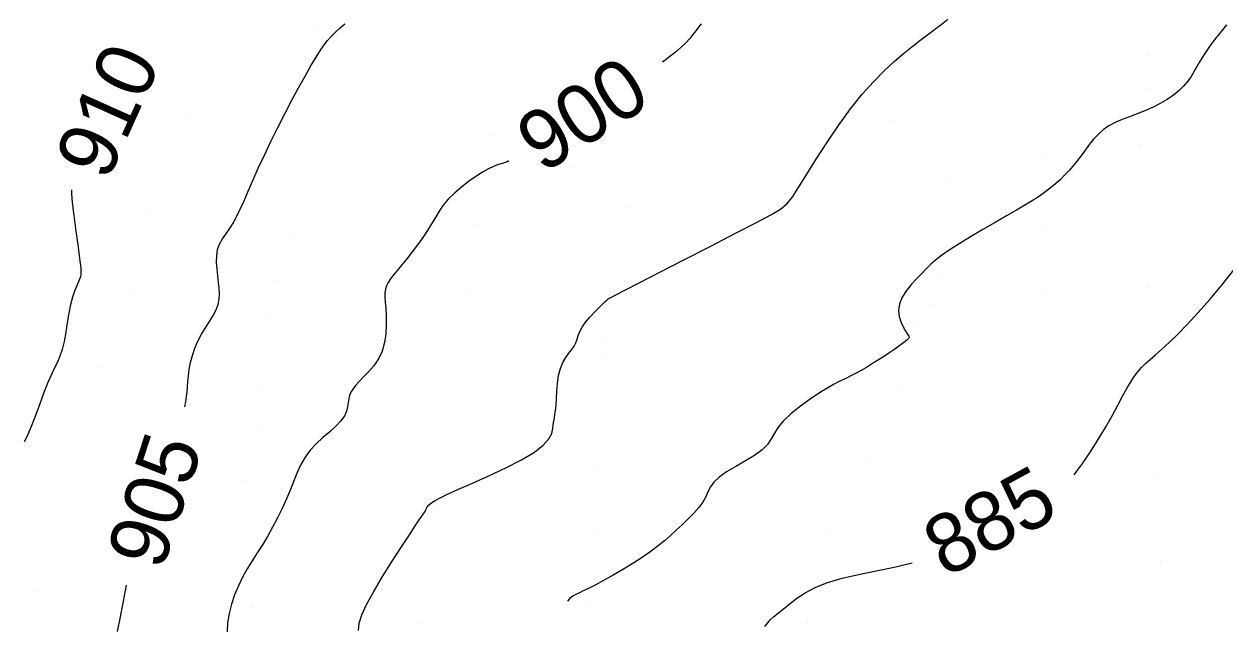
# Model space of a CAD drawing. Extents: x 400243 to 403697, y 4403637 to 4408083.
# Drawn here: x 402560 to 402712.4, y 4406302.1 to 4406378.5 of the extents above; entities that cross this region are included whole.
import ezdxf

# ---------------------------------------------------------------- set-up
doc = ezdxf.new("R2010")
doc.units = 0
doc.layers.add('HH_IC', color=7, linetype='Continuous')

msp = doc.modelspace()

# ---------------------------------------------------------------- linework, layer by layer
at = {"layer": 'HH_IC'}
for p, q in [((402596.95, 4406377.82), (402596.95, 4406377.82)), ((402613.38, 4406373.82), (402613.38, 4406373.82)), ((402702.61, 4406374.49), (402702.61, 4406374.49)), ((402689.11, 4406370.93), (402689.11, 4406370.93)), ((402702.76, 4406370.28), (402702.76, 4406370.28)), ((402599.34, 4406367.55), (402599.34, 4406367.55)), ((402580.57, 4406367), (402580.57, 4406367)), ((402670.6, 4406366.18), (402670.6, 4406366.18)), ((402619.51, 4406364.32), (402619.51, 4406364.32)), ((402701.52, 4406363.23), (402701.52, 4406363.23)), ((402689.31, 4406361.93), (402689.31, 4406361.93)), ((402621.3, 4406361.21), (402621.3, 4406361.21)), ((402629.18, 4406360.32), (402629.18, 4406360.32)), ((402676.82, 4406358.81), (402676.82, 4406358.81)), ((402631.27, 4406355.75), (402631.27, 4406355.75)), ((402575.44, 4406354.78), (402575.44, 4406354.78)), ((402636.48, 4406355.24), (402636.48, 4406355.24)), ((402656.96, 4406355.17), (402656.96, 4406355.17)), ((402702.32, 4406354.65), (402702.32, 4406354.65)), ((402617.11, 4406352.94), (402617.11, 4406352.94)), ((402689.86, 4406352.63), (402689.86, 4406352.63)), ((402594.46, 4406351.36), (402594.46, 4406351.36)), ((402675.85, 4406346.66), (402675.85, 4406346.66)), ((402592.23, 4406345.91), (402592.23, 4406345.91)), ((402616.71, 4406344.69), (402616.71, 4406344.69)), ((402702.71, 4406344.99), (402702.71, 4406344.99)), ((402573.45, 4406344.59), (402573.45, 4406344.59)), ((402634.3, 4406343.52), (402634.3, 4406343.52)), ((402689, 4406344.3), (402689, 4406344.3)), ((402674.7, 4406342.75), (402674.7, 4406342.75)), ((402591.18, 4406341.19), (402591.18, 4406341.19)), ((402672.69, 4406340.34), (402672.69, 4406340.34)), ((402633.27, 4406338.61), (402633.27, 4406338.61)), ((402672.01, 4406338.84), (402672.01, 4406338.84)), ((402633.12, 4406336.59), (402633.12, 4406336.59)), ((402688.71, 4406336.47), (402688.71, 4406336.47)), ((402569.46, 4406334.9), (402569.46, 4406334.9)), ((402703.95, 4406334.32), (402703.95, 4406334.32)), ((402589.51, 4406332.44), (402589.51, 4406332.44)), ((402616.6, 4406333.19), (402616.6, 4406333.19)), ((402670.72, 4406332.33), (402670.72, 4406332.33)), ((402616.39, 4406329.33), (402616.39, 4406329.33)), ((402589.51, 4406327.42), (402589.51, 4406327.42)), ((402633.22, 4406327.28), (402633.22, 4406327.28)), ((402562.54, 4406323.19), (402562.54, 4406323.19)), ((402632.98, 4406321.9), (402632.98, 4406321.9)), ((402667.03, 4406322.97), (402667.03, 4406322.97)), ((402688.37, 4406323.1), (402688.37, 4406323.1)), ((402588.12, 4406320.58), (402588.12, 4406320.58)), ((402704.09, 4406320.98), (402704.09, 4406320.98)), ((402566.86, 4406319.83), (402566.86, 4406319.83)), ((402612.5, 4406316.83), (402612.5, 4406316.83)), ((402632.05, 4406314.25), (402632.05, 4406314.25)), ((402661.86, 4406313.78), (402661.86, 4406313.78)), ((402688.7, 4406313.74), (402688.7, 4406313.74)), ((402586.21, 4406312.34), (402586.21, 4406312.34)), ((402704.19, 4406310.35), (402704.19, 4406310.35)), ((402565.85, 4406308.64), (402565.85, 4406308.64)), ((402561.34, 4406306.62), (402561.34, 4406306.62)), ((402631.28, 4406305.1), (402631.28, 4406305.1)), ((402588.95, 4406304.49), (402588.95, 4406304.49)), ((402686.63, 4406304.88), (402686.63, 4406304.88)), ((402610.09, 4406302.4), (402610.09, 4406302.4)), ((402659.33, 4406302.46), (402659.33, 4406302.46))]:
    msp.add_line(p, q, dxfattribs=at)
for points in [[(402580.4, 4406329.91), (402580.53, 4406330.57), (402580.62, 4406331.2), (402580.68, 4406331.82), (402580.72, 4406332.46), (402580.77, 4406333.13), (402580.84, 4406333.86), (402580.95, 4406334.67), (402581.12, 4406335.54), (402581.34, 4406336.44), (402581.64, 4406337.35), (402582.03, 4406338.25), (402582.5, 4406339.12), (402583.02, 4406339.95), (402583.53, 4406340.74), (402584, 4406341.5), (402584.38, 4406342.22), (402584.63, 4406342.9), (402584.76, 4406343.57), (402584.8, 4406344.24), (402584.76, 4406344.95), (402584.68, 4406345.7), (402584.57, 4406346.52), (402584.47, 4406347.38), (402584.41, 4406348.25), (402584.43, 4406349.09), (402584.55, 4406349.88), (402584.8, 4406350.57), (402585.15, 4406351.22), (402585.57, 4406351.84), (402586.04, 4406352.5), (402586.51, 4406353.22), (402586.96, 4406354.04), (402587.42, 4406354.98), (402587.9, 4406356.05), (402588.42, 4406357.27), (402589.02, 4406358.65), (402589.71, 4406360.19), (402590.48, 4406361.85), (402591.3, 4406363.59), (402592.17, 4406365.36), (402593.06, 4406367.11), (402593.95, 4406368.81), (402594.82, 4406370.4), (402595.64, 4406371.87), (402596.39, 4406373.18), (402597.06, 4406374.28), (402597.61, 4406375.16), (402598.08, 4406375.85), (402598.48, 4406376.4), (402598.86, 4406376.84), (402599.23, 4406377.22), (402599.63, 4406377.59), (402600.1, 4406378), (402600.69, 4406378.52)], [(402602.41, 4406301.53), (402602.52, 4406302.44), (402602.84, 4406303.5), (402603.44, 4406304.83), (402604.35, 4406306.49), (402605.48, 4406308.38), (402606.69, 4406310.32), (402607.87, 4406312.14), (402608.88, 4406313.67), (402609.62, 4406314.79), (402610.13, 4406315.55), (402610.45, 4406316.02), (402610.64, 4406316.29), (402610.75, 4406316.47), (402610.84, 4406316.6), (402610.91, 4406316.73), (402610.97, 4406316.84), (402611.01, 4406316.93), (402611.05, 4406317.03), (402611.09, 4406317.11), (402611.13, 4406317.2), (402611.21, 4406317.31), (402611.32, 4406317.43), (402611.49, 4406317.57), (402611.74, 4406317.76), (402612.14, 4406318.01), (402612.78, 4406318.35), (402613.73, 4406318.82), (402615.09, 4406319.45), (402616.89, 4406320.24), (402618.96, 4406321.16), (402621.1, 4406322.16), (402623.09, 4406323.18), (402624.74, 4406324.15), (402625.87, 4406325.04), (402626.56, 4406325.83), (402626.93, 4406326.53), (402627.08, 4406327.14), (402627.14, 4406327.66), (402627.2, 4406328.1), (402627.27, 4406328.51), (402627.35, 4406328.94), (402627.42, 4406329.45), (402627.49, 4406330.11), (402627.54, 4406330.94), (402627.59, 4406331.89), (402627.67, 4406332.9), (402627.81, 4406333.89), (402628.03, 4406334.79), (402628.34, 4406335.55), (402628.72, 4406336.18), (402629.11, 4406336.71), (402629.48, 4406337.18), (402629.79, 4406337.62), (402630, 4406338.05), (402630.15, 4406338.49), (402630.3, 4406338.96), (402630.49, 4406339.47), (402630.79, 4406340.03), (402631.23, 4406340.65), (402631.77, 4406341.29), (402632.35, 4406341.91), (402632.9, 4406342.48), (402633.38, 4406342.94), (402633.72, 4406343.26), (402633.95, 4406343.48), (402634.09, 4406343.6), (402634.17, 4406343.66), (402634.21, 4406343.69), (402634.28, 4406343.72), (402634.51, 4406343.84), (402635.09, 4406344.13), (402636.21, 4406344.7), (402638.02, 4406345.64), (402640.64, 4406346.98), (402643.79, 4406348.6), (402647.12, 4406350.32), (402650.27, 4406351.94), (402652.9, 4406353.3), (402654.75, 4406354.28), (402655.96, 4406355), (402656.78, 4406355.66), (402657.43, 4406356.47), (402658.16, 4406357.61), (402659.17, 4406359.23), (402660.41, 4406361.21), (402661.83, 4406363.4), (402663.33, 4406365.62), (402664.86, 4406367.73), (402666.34, 4406369.57), (402667.75, 4406371.17), (402669.1, 4406372.54), (402670.36, 4406373.71), (402671.55, 4406374.73), (402672.64, 4406375.61), (402673.66, 4406376.4), (402674.61, 4406377.12), (402675.5, 4406377.79), (402676.35, 4406378.45), (402677.18, 4406379.12)], [(402712.56, 4406378.38), (402711.92, 4406377.58), (402711.29, 4406376.81), (402710.7, 4406376.07), (402710.2, 4406375.39), (402709.78, 4406374.77), (402709.42, 4406374.17), (402709.08, 4406373.6), (402708.76, 4406373.02), (402708.42, 4406372.44), (402708.05, 4406371.84), (402707.63, 4406371.24), (402707.13, 4406370.65), (402706.53, 4406370.05), (402705.82, 4406369.47), (402705, 4406368.92), (402704.11, 4406368.39), (402703.16, 4406367.9), (402702.18, 4406367.46), (402701.2, 4406367.08), (402700.23, 4406366.72), (402699.29, 4406366.37), (402698.41, 4406365.99), (402697.6, 4406365.56), (402696.88, 4406365.05), (402696.25, 4406364.48), (402695.69, 4406363.87), (402695.18, 4406363.25), (402694.73, 4406362.64), (402694.3, 4406362.06), (402693.89, 4406361.51), (402693.48, 4406360.97), (402693.05, 4406360.44), (402692.57, 4406359.9), (402692.05, 4406359.34), (402691.47, 4406358.77), (402690.84, 4406358.2), (402690.17, 4406357.64), (402689.46, 4406357.1), (402688.71, 4406356.58), (402687.89, 4406356.05), (402686.97, 4406355.49), (402685.9, 4406354.87), (402684.64, 4406354.14), (402683.2, 4406353.31), (402681.64, 4406352.4), (402680.08, 4406351.48), (402678.61, 4406350.59), (402677.36, 4406349.79), (402676.38, 4406349.12), (402675.64, 4406348.54), (402675.04, 4406348.01), (402674.5, 4406347.48), (402673.93, 4406346.89), (402673.28, 4406346.22), (402672.59, 4406345.46), (402671.95, 4406344.66), (402671.41, 4406343.82), (402671.06, 4406342.98), (402670.95, 4406342.15), (402671.03, 4406341.38), (402671.24, 4406340.68), (402671.51, 4406340.07), (402671.78, 4406339.59), (402672, 4406339.25), (402672.15, 4406339.02), (402672.25, 4406338.88), (402672.3, 4406338.79), (402672.3, 4406338.72), (402672.26, 4406338.63), (402672.17, 4406338.52), (402672.01, 4406338.38), (402671.77, 4406338.18), (402671.43, 4406337.93), (402670.99, 4406337.61), (402670.45, 4406337.23), (402669.84, 4406336.8), (402669.15, 4406336.34), (402668.41, 4406335.87), (402667.64, 4406335.39), (402666.86, 4406334.92), (402666.1, 4406334.48), (402665.41, 4406334.1), (402664.81, 4406333.79), (402664.32, 4406333.55), (402663.87, 4406333.35), (402663.39, 4406333.12), (402662.78, 4406332.8), (402661.98, 4406332.33), (402660.93, 4406331.67), (402659.73, 4406330.87), (402658.48, 4406329.98), (402657.32, 4406329.05), (402656.35, 4406328.15), (402655.68, 4406327.32), (402655.2, 4406326.55), (402654.78, 4406325.83), (402654.3, 4406325.14), (402653.62, 4406324.45), (402652.66, 4406323.75), (402651.51, 4406323.05), (402650.29, 4406322.35), (402649.13, 4406321.66), (402648.18, 4406321), (402647.51, 4406320.36), (402647.07, 4406319.74), (402646.75, 4406319.13), (402646.47, 4406318.49), (402646.11, 4406317.83), (402645.61, 4406317.14), (402644.97, 4406316.41), (402644.26, 4406315.68), (402643.49, 4406314.95), (402642.73, 4406314.24), (402641.99, 4406313.57), (402641.25, 4406312.91), (402640.45, 4406312.26), (402639.57, 4406311.58), (402638.54, 4406310.86), (402637.34, 4406310.09), (402636.05, 4406309.3), (402634.74, 4406308.54), (402633.51, 4406307.85), (402632.44, 4406307.28), (402631.59, 4406306.85), (402630.94, 4406306.54), (402630.45, 4406306.32), (402630.07, 4406306.14), (402629.75, 4406305.96), (402629.45, 4406305.75), (402629.19, 4406305.52), (402628.95, 4406305.25)], [(402645.91, 4406378.51), (402645.57, 4406378.08), (402645.23, 4406377.63), (402644.86, 4406377.16), (402644.44, 4406376.66), (402643.94, 4406376.12), (402643.34, 4406375.55), (402642.64, 4406374.94), (402641.86, 4406374.31), (402641, 4406373.65)], [(402621.5, 4406361.11), (402621.45, 4406361.09), (402621.4, 4406361.06), (402621.32, 4406361.03), (402621.21, 4406360.98), (402621.04, 4406360.93), (402620.8, 4406360.85), (402620.47, 4406360.76), (402620.05, 4406360.62), (402619.53, 4406360.41), (402618.9, 4406360.11), (402618.16, 4406359.7), (402617.31, 4406359.16), (402616.39, 4406358.52), (402615.47, 4406357.8), (402614.59, 4406357.03), (402613.81, 4406356.26), (402613.18, 4406355.49), (402612.64, 4406354.73), (402612.17, 4406353.95), (402611.69, 4406353.15), (402611.17, 4406352.3), (402610.57, 4406351.4), (402609.91, 4406350.48), (402609.23, 4406349.57), (402608.55, 4406348.7), (402607.91, 4406347.92), (402607.36, 4406347.24), (402606.88, 4406346.66), (402606.49, 4406346.16), (402606.18, 4406345.7), (402605.96, 4406345.27), (402605.84, 4406344.84), (402605.78, 4406344.39), (402605.78, 4406343.85), (402605.82, 4406343.21), (402605.88, 4406342.42), (402605.93, 4406341.46), (402605.95, 4406340.37), (402605.9, 4406339.22), (402605.74, 4406338.07), (402605.43, 4406336.98), (402604.96, 4406335.99), (402604.36, 4406335.13), (402603.71, 4406334.36), (402603.07, 4406333.7), (402602.5, 4406333.12), (402602.04, 4406332.62), (402601.7, 4406332.17), (402601.46, 4406331.76), (402601.29, 4406331.35), (402601.18, 4406330.91), (402601.11, 4406330.44), (402601.03, 4406329.91), (402600.89, 4406329.35), (402600.63, 4406328.75), (402600.19, 4406328.12), (402599.56, 4406327.45), (402598.77, 4406326.75), (402597.91, 4406326.01), (402597.06, 4406325.22), (402596.28, 4406324.39), (402595.64, 4406323.5), (402595.12, 4406322.57), (402594.66, 4406321.57), (402594.23, 4406320.52), (402593.78, 4406319.41), (402593.29, 4406318.23), (402592.74, 4406317.02), (402592.15, 4406315.81), (402591.53, 4406314.62), (402590.89, 4406313.47), (402590.23, 4406312.4), (402589.58, 4406311.37), (402588.93, 4406310.37), (402588.31, 4406309.35), (402587.72, 4406308.3), (402587.18, 4406307.19), (402586.7, 4406306.04), (402586.31, 4406304.86), (402586.01, 4406303.67), (402585.82, 4406302.49), (402585.75, 4406301.34)], [(402566.02, 4406357.46), (402566.03, 4406356.92), (402566.06, 4406356.4), (402566.11, 4406355.84), (402566.18, 4406355.21), (402566.28, 4406354.47), (402566.39, 4406353.57), (402566.53, 4406352.51), (402566.69, 4406351.34), (402566.84, 4406350.16), (402566.98, 4406349.07), (402567.1, 4406348.16), (402567.18, 4406347.49), (402567.21, 4406347.02), (402567.2, 4406346.68), (402567.14, 4406346.4), (402567.02, 4406346.09), (402566.85, 4406345.7), (402566.63, 4406345.2), (402566.39, 4406344.58), (402566.14, 4406343.81), (402565.9, 4406342.88), (402565.68, 4406341.78), (402565.48, 4406340.59), (402565.28, 4406339.37), (402565.06, 4406338.21), (402564.83, 4406337.18), (402564.55, 4406336.32), (402564.23, 4406335.58), (402563.87, 4406334.85), (402563.47, 4406334.02), (402563.01, 4406333), (402562.51, 4406331.73), (402561.98, 4406330.29), (402561.44, 4406328.81), (402560.9, 4406327.4), (402560.38, 4406326.19), (402559.99, 4406325.46)], [(402693.2, 4406321.29), (402694.27, 4406322.71), (402695.31, 4406324.21), (402696.28, 4406325.77), (402697.19, 4406327.3), (402698.02, 4406328.77), (402698.75, 4406330.1), (402699.37, 4406331.25), (402699.91, 4406332.23), (402700.4, 4406333.06), (402700.85, 4406333.76), (402701.3, 4406334.37), (402701.76, 4406334.89), (402702.27, 4406335.39), (402702.85, 4406335.9), (402703.53, 4406336.49), (402704.34, 4406337.21), (402705.29, 4406338.09), (402706.39, 4406339.15), (402707.61, 4406340.4), (402708.96, 4406341.86), (402710.42, 4406343.52), (402711.96, 4406345.37), (402713.52, 4406347.32)], [(402653.99, 4406302.01), (402654.35, 4406302.51), (402654.7, 4406302.91), (402655.07, 4406303.25), (402655.49, 4406303.58), (402655.96, 4406303.96), (402656.53, 4406304.41), (402657.21, 4406304.97), (402658.05, 4406305.62), (402659.08, 4406306.3), (402660.36, 4406306.98), (402661.91, 4406307.6), (402663.77, 4406308.15), (402665.86, 4406308.63), (402668.1, 4406309.09), (402670.4, 4406309.57), (402672.67, 4406310.11)], [(402571.85, 4406301.4), (402572.22, 4406303.27), (402572.6, 4406305.26), (402572.99, 4406307.26)]]:
    msp.add_lwpolyline(points, dxfattribs=at)

# ---------------------------------------------------------------- texts
for s, rotation, p in [('910', 65.7948, (402570.54, 4406358.37)), ('900', 32.7399, (402625.79, 4406359.41)), ('905', 71.8777, (402577.49, 4406308.96)), ('885', 28.5924, (402676.91, 4406308.15))]:
    msp.add_text(s, height=7.5, rotation=rotation, dxfattribs=at).set_placement(p)

doc.saveas('drawing.dxf')
